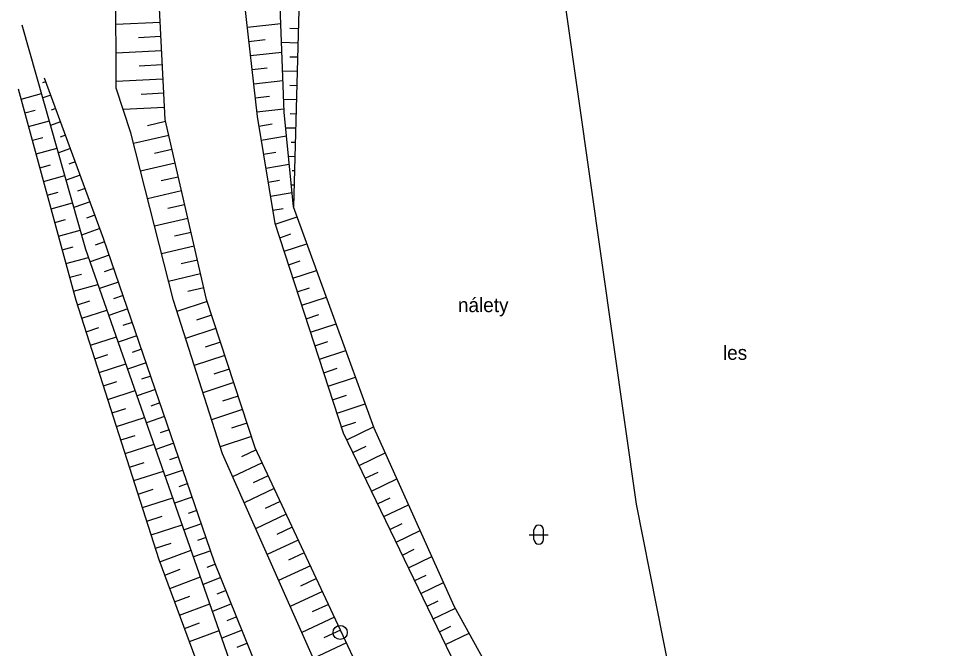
# Model space of a CAD drawing. Extents: x -762483 to -761175, y -1154655 to -1152452.
# Drawn here: x -761528.36 to -761479.5, y -1153577.24 to -1153543.98 of the extents above; entities that cross this region are included whole.
import ezdxf

# ---------------------------------------------------------------- set-up
doc = ezdxf.new("R2010")
doc.units = 0
for name, color, linetype in [('MAP_ZN_BP', 7, 'Continuous'), ('ROZHRANÍ_PLOCH', 7, 'Continuous'), ('VÝŠKOPIS', 7, 'Continuous'), ('ZELEŇ', 7, 'Continuous'), ('ZN_KULTUR', 7, 'Continuous')]:
    doc.layers.add(name, color=color, linetype=linetype)

msp = doc.modelspace()

# ---------------------------------------------------------------- linework, layer by layer
at = {"layer": 'MAP_ZN_BP'}
for radius in [0.375, 0.0005]:
    msp.add_circle((-761511.37, -1153576.39), radius, dxfattribs=at)
at = {"layer": 'ROZHRANÍ_PLOCH'}
for points in [[(-761473.21, -1153684.07), (-761469.46, -1153679.5), (-761466.97, -1153675.46), (-761465.27, -1153671.92), (-761464.53, -1153668.61), (-761464.73, -1153664.68), (-761466, -1153658.71), (-761468.55, -1153651.77), (-761473.7, -1153641.76), (-761483.81, -1153624.91), (-761489.13, -1153616.22), (-761501.02, -1153596.18), (-761505.16, -1153588.62), (-761508.76, -1153581.79), (-761515.86, -1153566.65), (-761518.43, -1153558.82), (-761520.62, -1153549.31), (-761520.92, -1153543.45), (-761519.67, -1153527.09), (-761518.4, -1153518.01), (-761514.9, -1153498.24), (-761512.46, -1153485.54), (-761510.57, -1153476.01), (-761507.02, -1153459.49)], [(-761452.11, -1153680.09), (-761455.06, -1153677.36), (-761457.46, -1153672.86), (-761459.23, -1153668.13), (-761461.75, -1153656.48), (-761464.72, -1153649.83), (-761470.08, -1153639.37), (-761481.24, -1153620.57), (-761493.92, -1153599.29), (-761502.78, -1153583.29), (-761511.19, -1153565.87), (-761514.81, -1153554.8), (-761515.74, -1153549.15), (-761516.42, -1153543.11), (-761515.79, -1153528.81), (-761514.01, -1153518.23), (-761510.25, -1153496.92), (-761507.85, -1153485.44), (-761506.02, -1153476.2), (-761502.85, -1153460.41)]]:
    msp.add_lwpolyline(points, dxfattribs=at)
at = {"layer": 'VÝŠKOPIS'}
for p, q in [((-761520.882, -1153544.186), (-761523.212, -1153544.305)), ((-761516.27, -1153544.446), (-761514.506, -1153544.247)), ((-761513.574, -1153544.528), (-761514.035, -1153544.516)), ((-761520.844, -1153544.935), (-761522.027, -1153544.995)), ((-761516.186, -1153545.191), (-761515.332, -1153545.095)), ((-761513.594, -1153545.278), (-761514.468, -1153545.254)), ((-761520.806, -1153545.684), (-761523.207, -1153545.806)), ((-761516.102, -1153545.936), (-761514.45, -1153545.75)), ((-761513.615, -1153546.028), (-761514.027, -1153546.017)), ((-761520.767, -1153546.433), (-761521.986, -1153546.495)), ((-761516.018, -1153546.681), (-761515.22, -1153546.592)), ((-761520.729, -1153547.182), (-761523.201, -1153547.308)), ((-761513.635, -1153546.778), (-761514.412, -1153546.756)), ((-761526.911, -1153547.318), (-761527.094, -1153547.385)), ((-761515.934, -1153547.427), (-761514.393, -1153547.253)), ((-761513.656, -1153547.527), (-761514.02, -1153547.517)), ((-761528.219, -1153548.238), (-761527.138, -1153547.943)), ((-761526.652, -1153548.022), (-761527.072, -1153548.176)), ((-761520.691, -1153547.931), (-761521.881, -1153547.992)), ((-761515.85, -1153548.172), (-761515.107, -1153548.088)), ((-761520.652, -1153548.68), (-761522.831, -1153548.791)), ((-761513.676, -1153548.277), (-761514.355, -1153548.259)), ((-761528.022, -1153548.961), (-761527.478, -1153548.813)), ((-761526.393, -1153548.726), (-761526.63, -1153548.813)), ((-761515.766, -1153548.917), (-761514.337, -1153548.756)), ((-761513.696, -1153549.027), (-761514.009, -1153549.018)), ((-761527.824, -1153549.685), (-761526.729, -1153549.386)), ((-761526.135, -1153549.43), (-761526.662, -1153549.624)), ((-761520.593, -1153549.426), (-761521.538, -1153549.643)), ((-761515.656, -1153549.659), (-761514.968, -1153549.546)), ((-761525.876, -1153550.134), (-761526.167, -1153550.24)), ((-761520.425, -1153550.157), (-761522.286, -1153550.585)), ((-761513.717, -1153549.777), (-761514.247, -1153549.762)), ((-761527.627, -1153550.409), (-761527.076, -1153550.258)), ((-761515.534, -1153550.399), (-761514.205, -1153550.18)), ((-761513.737, -1153550.526), (-761513.954, -1153550.52)), ((-761527.43, -1153551.132), (-761526.321, -1153550.83)), ((-761525.617, -1153550.837), (-761526.253, -1153551.071)), ((-761520.257, -1153550.888), (-761521.179, -1153551.1)), ((-761515.413, -1153551.139), (-761514.771, -1153551.034)), ((-761525.358, -1153551.541), (-761525.703, -1153551.668)), ((-761520.088, -1153551.618), (-761521.917, -1153552.039)), ((-761513.758, -1153551.276), (-761514.096, -1153551.267)), ((-761527.232, -1153551.856), (-761526.675, -1153551.704)), ((-761515.291, -1153551.879), (-761514.055, -1153551.676)), ((-761513.778, -1153552.026), (-761513.9, -1153552.022)), ((-761527.035, -1153552.579), (-761525.913, -1153552.273)), ((-761525.1, -1153552.245), (-761525.843, -1153552.519)), ((-761519.92, -1153552.349), (-761520.826, -1153552.558)), ((-761515.169, -1153552.619), (-761514.575, -1153552.521)), ((-761524.841, -1153552.949), (-761525.24, -1153553.096)), ((-761519.752, -1153553.08), (-761521.547, -1153553.494)), ((-761513.799, -1153552.775), (-761513.946, -1153552.771)), ((-761526.838, -1153553.303), (-761526.273, -1153553.149)), ((-761515.047, -1153553.359), (-761513.906, -1153553.171)), ((-761526.641, -1153554.027), (-761525.504, -1153553.717)), ((-761524.582, -1153553.653), (-761525.434, -1153553.966)), ((-761519.583, -1153553.811), (-761520.473, -1153554.016)), ((-761514.925, -1153554.099), (-761514.378, -1153554.009)), ((-761524.323, -1153554.357), (-761524.776, -1153554.524)), ((-761519.415, -1153554.542), (-761521.177, -1153554.948)), ((-761514.798, -1153554.838), (-761513.638, -1153554.459)), ((-761526.443, -1153554.75), (-761525.872, -1153554.594)), ((-761526.246, -1153555.474), (-761525.096, -1153555.16)), ((-761524.064, -1153555.061), (-761525.024, -1153555.414)), ((-761519.247, -1153555.273), (-761520.12, -1153555.474)), ((-761514.564, -1153555.551), (-761513.973, -1153555.357)), ((-761523.809, -1153555.766), (-761524.317, -1153555.941)), ((-761519.079, -1153556.004), (-761520.808, -1153556.402)), ((-761514.331, -1153556.264), (-761513.124, -1153555.869)), ((-761526.049, -1153556.197), (-761525.47, -1153556.04)), ((-761523.566, -1153556.476), (-761524.58, -1153556.824)), ((-761525.851, -1153556.921), (-761524.66, -1153556.596)), ((-761518.91, -1153556.734), (-761519.766, -1153556.932)), ((-761514.098, -1153556.976), (-761513.483, -1153556.775)), ((-761525.654, -1153557.644), (-761525.033, -1153557.475)), ((-761523.322, -1153557.185), (-761523.827, -1153557.359)), ((-761518.742, -1153557.465), (-761520.438, -1153557.856)), ((-761513.865, -1153557.689), (-761512.61, -1153557.279)), ((-761523.078, -1153557.894), (-761524.084, -1153558.24)), ((-761525.457, -1153558.368), (-761524.163, -1153558.015)), ((-761518.574, -1153558.196), (-761519.413, -1153558.39)), ((-761513.632, -1153558.402), (-761512.993, -1153558.193)), ((-761525.25, -1153559.089), (-761524.592, -1153558.878)), ((-761522.835, -1153558.604), (-761523.335, -1153558.776)), ((-761518.396, -1153558.924), (-761519.995, -1153559.449)), ((-761513.399, -1153559.115), (-761512.097, -1153558.689)), ((-761525.021, -1153559.803), (-761523.686, -1153559.375)), ((-761522.591, -1153559.313), (-761523.587, -1153559.655)), ((-761518.162, -1153559.637), (-761518.964, -1153559.9)), ((-761513.166, -1153559.828), (-761512.503, -1153559.611)), ((-761524.792, -1153560.517), (-761524.115, -1153560.3)), ((-761522.348, -1153560.022), (-761522.843, -1153560.193)), ((-761517.928, -1153560.35), (-761519.538, -1153560.878)), ((-761512.933, -1153560.541), (-761511.583, -1153560.099)), ((-761524.563, -1153561.231), (-761523.189, -1153560.791)), ((-761522.104, -1153560.732), (-761523.091, -1153561.071)), ((-761517.694, -1153561.062), (-761518.502, -1153561.327)), ((-761512.7, -1153561.254), (-761512.013, -1153561.029)), ((-761524.334, -1153561.945), (-761523.637, -1153561.722)), ((-761521.86, -1153561.441), (-761522.351, -1153561.61)), ((-761517.46, -1153561.775), (-761519.081, -1153562.307)), ((-761512.467, -1153561.966), (-761511.07, -1153561.51)), ((-761524.105, -1153562.66), (-761522.692, -1153562.207)), ((-761521.617, -1153562.15), (-761522.594, -1153562.486)), ((-761521.373, -1153562.86), (-761521.859, -1153563.027)), ((-761517.226, -1153562.487), (-761518.039, -1153562.754)), ((-761512.233, -1153562.679), (-761511.523, -1153562.447)), ((-761523.876, -1153563.374), (-761523.16, -1153563.144)), ((-761516.992, -1153563.2), (-761518.624, -1153563.736)), ((-761512, -1153563.392), (-761510.556, -1153562.92)), ((-761523.647, -1153564.088), (-761522.195, -1153563.623)), ((-761521.129, -1153563.569), (-761522.098, -1153563.902)), ((-761520.886, -1153564.278), (-761521.368, -1153564.444)), ((-761516.758, -1153563.913), (-761517.577, -1153564.181)), ((-761511.767, -1153564.105), (-761511.033, -1153563.865)), ((-761511.534, -1153564.818), (-761510.042, -1153564.33)), ((-761523.418, -1153564.802), (-761522.682, -1153564.566)), ((-761516.525, -1153564.625), (-761518.167, -1153565.164)), ((-761523.189, -1153565.516), (-761521.699, -1153565.039)), ((-761520.642, -1153564.988), (-761521.601, -1153565.317)), ((-761511.301, -1153565.531), (-761510.543, -1153565.283)), ((-761520.399, -1153565.697), (-761520.876, -1153565.861)), ((-761516.291, -1153565.338), (-761517.115, -1153565.608)), ((-761511.019, -1153566.224), (-761509.602, -1153565.54)), ((-761522.96, -1153566.231), (-761522.205, -1153565.989)), ((-761516.057, -1153566.05), (-761517.71, -1153566.593)), ((-761522.731, -1153566.945), (-761521.202, -1153566.455)), ((-761520.155, -1153566.406), (-761521.104, -1153566.732)), ((-761515.81, -1153566.758), (-761516.585, -1153567.121)), ((-761510.693, -1153566.899), (-761509.996, -1153566.563)), ((-761519.911, -1153567.116), (-761520.384, -1153567.278)), ((-761510.367, -1153567.575), (-761508.99, -1153566.91)), ((-761522.502, -1153567.659), (-761521.728, -1153567.411)), ((-761515.491, -1153567.437), (-761517.056, -1153568.171)), ((-761522.273, -1153568.373), (-761520.705, -1153567.87)), ((-761519.668, -1153567.825), (-761520.608, -1153568.148)), ((-761515.173, -1153568.116), (-761515.962, -1153568.486)), ((-761510.041, -1153568.25), (-761509.361, -1153567.922)), ((-761519.424, -1153568.534), (-761519.892, -1153568.695)), ((-761509.715, -1153568.926), (-761508.373, -1153568.278)), ((-761522.044, -1153569.087), (-761521.25, -1153568.833)), ((-761514.854, -1153568.795), (-761516.447, -1153569.542)), ((-761521.815, -1153569.801), (-761520.208, -1153569.286)), ((-761519.18, -1153569.244), (-761520.111, -1153569.563)), ((-761514.536, -1153569.474), (-761515.339, -1153569.85)), ((-761509.389, -1153569.601), (-761508.727, -1153569.281)), ((-761509.063, -1153570.276), (-761507.757, -1153569.646)), ((-761518.937, -1153569.953), (-761519.4, -1153570.112)), ((-761514.217, -1153570.153), (-761515.837, -1153570.913)), ((-761521.586, -1153570.516), (-761520.773, -1153570.255)), ((-761518.693, -1153570.662), (-761519.615, -1153570.979)), ((-761508.737, -1153570.952), (-761508.093, -1153570.641)), ((-761521.357, -1153571.23), (-761519.712, -1153570.702)), ((-761513.899, -1153570.832), (-761514.716, -1153571.215)), ((-761508.411, -1153571.627), (-761507.141, -1153571.014)), ((-761518.449, -1153571.372), (-761518.908, -1153571.529)), ((-761513.58, -1153571.511), (-761515.228, -1153572.284)), ((-761521.128, -1153571.944), (-761520.295, -1153571.677)), ((-761520.894, -1153572.657), (-761519.241, -1153572.044)), ((-761518.206, -1153572.081), (-761519.118, -1153572.394)), ((-761508.084, -1153572.303), (-761507.458, -1153572)), ((-761513.262, -1153572.19), (-761514.093, -1153572.58)), ((-761507.758, -1153572.978), (-761506.524, -1153572.382)), ((-761520.634, -1153573.36), (-761519.813, -1153573.056)), ((-761517.956, -1153572.788), (-761518.405, -1153572.969)), ((-761512.944, -1153572.869), (-761514.619, -1153573.655)), ((-761520.373, -1153574.063), (-761518.746, -1153573.46)), ((-761517.676, -1153573.484), (-761518.607, -1153573.86)), ((-761512.625, -1153573.548), (-761513.47, -1153573.944)), ((-761507.432, -1153573.653), (-761506.824, -1153573.36)), ((-761507.106, -1153574.329), (-761505.908, -1153573.75)), ((-761520.112, -1153574.766), (-761519.306, -1153574.467)), ((-761517.395, -1153574.179), (-761517.877, -1153574.374)), ((-761512.307, -1153574.227), (-761514.009, -1153575.026)), ((-761519.852, -1153575.47), (-761518.252, -1153574.877)), ((-761517.114, -1153574.874), (-761518.112, -1153575.277)), ((-761511.988, -1153574.906), (-761512.846, -1153575.309)), ((-761506.78, -1153575.004), (-761506.19, -1153574.719)), ((-761516.833, -1153575.57), (-761517.349, -1153575.778)), ((-761506.454, -1153575.68), (-761505.283, -1153575.114)), ((-761519.591, -1153576.173), (-761518.798, -1153575.879)), ((-761511.67, -1153575.585), (-761513.4, -1153576.397)), ((-761506.128, -1153576.355), (-761505.524, -1153576.063)), ((-761519.33, -1153576.876), (-761517.758, -1153576.293)), ((-761516.552, -1153576.265), (-761517.618, -1153576.695)), ((-761511.351, -1153576.264), (-761512.223, -1153576.673)), ((-761505.802, -1153577.03), (-761504.556, -1153576.429)), ((-761516.271, -1153576.961), (-761516.821, -1153577.183)), ((-761511.033, -1153576.943), (-761512.79, -1153577.767))]:
    msp.add_line(p, q, dxfattribs=at)
for points in [[(-761507.72, -1153504.64), (-761513.14, -1153528.59), (-761513.83, -1153553.93)], [(-761472.39, -1153633.33), (-761479.86, -1153619.77), (-761492.52, -1153598.23), (-761505.34, -1153575.01), (-761509.58, -1153565.6), (-761513.83, -1153553.93), (-761514.33, -1153548.93), (-761514.54, -1153543.35), (-761514.65, -1153531.04), (-761510.51, -1153505.03)], [(-761479.87, -1153657.21), (-761481.77, -1153653.84), (-761499.98, -1153616.6), (-761506.82, -1153602.08), (-761511.92, -1153593.03), (-761519.06, -1153572.56), (-761524.81, -1153556.17), (-761528.16, -1153544.33)], [(-761474.97, -1153672.67), (-761481.14, -1153657.53), (-761482.71, -1153655.62), (-761499.8, -1153620.02), (-761506.98, -1153606.58), (-761512.98, -1153594.01), (-761520.93, -1153572.56), (-761525.32, -1153558.87), (-761528.36, -1153547.72)]]:
    msp.add_lwpolyline(points, dxfattribs=at)
at = {"layer": 'ZELEŇ'}
for points in [[(-761472.39, -1153633.33), (-761479.21, -1153619.43), (-761487.13, -1153604.92), (-761490.34, -1153596.71), (-761495.72, -1153569.61), (-761500.02, -1153539.43), (-761507.72, -1153504.64)], [(-761509.98, -1153584.09), (-761517.59, -1153566.97), (-761520.18, -1153558.87), (-761522.43, -1153550.02), (-761523.2, -1153547.66), (-761523.22, -1153542.15)], [(-761506.79, -1153599.82), (-761509.92, -1153592.69), (-761518, -1153572.68), (-761523.87, -1153555.59), (-761526.98, -1153547.13)]]:
    msp.add_lwpolyline(points, dxfattribs=at)
at = {"layer": 'ZN_KULTUR'}
for p, q in [((-761501.13, -1153571.48), (-761501.13, -1153570.98)), ((-761500.63, -1153571.48), (-761500.63, -1153570.98)), ((-761501.38, -1153571.23), (-761500.38, -1153571.23))]:
    msp.add_line(p, q, dxfattribs=at)
for centre, start, end in [((-761500.88, -1153570.98), 0, 180), ((-761500.88, -1153571.48), 180, 360)]:
    msp.add_arc(centre, 0.25, start, end, dxfattribs=at)

# ---------------------------------------------------------------- texts
at = {"layer": 'ZELEŇ'}
for s, p in [('nálety', (-761505.15, -1153559.48)), ('les', (-761491.15, -1153562))]:
    msp.add_text(s, height=0.75, dxfattribs=at).set_placement(p)

doc.saveas('drawing.dxf')
